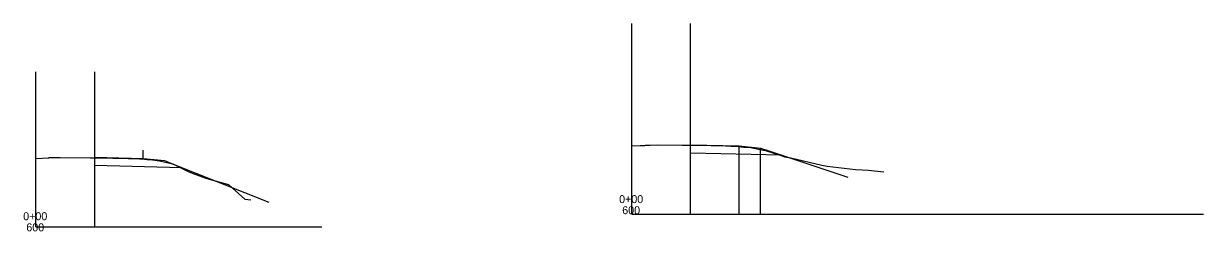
# Model space of a CAD drawing. Extents: x 2376379 to 2383101, y 559608 to 561720.
# Drawn here: x 2377931 to 2378343.8, y 561400.7 to 561473.6 of the extents above; entities that cross this region are included whole.
import ezdxf

# ---------------------------------------------------------------- set-up
doc = ezdxf.new("R2010")
doc.units = 0
for name, color, linetype in [('DT_X_Contour_Minor', 7, 'Continuous'), ('PV_X_Driveway', 7, 'Continuous'), ('SV_X_Text', 7, 'Continuous')]:
    doc.layers.add(name, color=color, linetype=linetype)

msp = doc.modelspace()

# ---------------------------------------------------------------- linework, layer by layer
at = {"layer": 'PV_X_Driveway'}
for points in [[(2378143.79, 561430.65), (2378146.66, 561430.83), (2378148.35, 561430.85), (2378148.54, 561430.93), (2378150.21, 561430.98), (2378152.65, 561430.99), (2378161.38, 561430.93), (2378164.12, 561430.92), (2378166.6, 561430.89), (2378176.62, 561430.7), (2378178.51, 561430.61), (2378180.39, 561430.55), (2378181.06, 561430.42), (2378182.95, 561430.25), (2378184.95, 561430.17), (2378188.59, 561429.37), (2378190.62, 561429.07), (2378196.1, 561427.35), (2378197.27, 561426.88), (2378199.45, 561426.43), (2378210.23, 561423.92), (2378212.16, 561423.57), (2378222.08, 561422.41), (2378226.57, 561422.17), (2378231.93, 561421.59)], [(2377935.28, 561426.24), (2377939.81, 561426.54), (2377939.87, 561426.56), (2377940.21, 561426.63), (2377941.64, 561426.64), (2377943.8, 561426.64), (2377954.28, 561426.51), (2377955.51, 561426.52), (2377956.81, 561426.49), (2377967.62, 561426.27), (2377970, 561426.22), (2377971.49, 561426.17), (2377971.76, 561426.15), (2377972.4, 561426.18), (2377974.2, 561425.93), (2377976.04, 561425.73), (2377978.54, 561425.44), (2377979.03, 561425.29), (2377983.25, 561424.34), (2377988.58, 561421.75), (2377989.94, 561421.12), (2377994.78, 561419.37), (2377996.71, 561418.8), (2378002.7, 561417.18), (2378004, 561416), (2378008.36, 561412.03), (2378010.47, 561411.72)]]:
    msp.add_lwpolyline(points, dxfattribs=at)
at = {"layer": 'SV_X_Text'}
for p, q in [((2378143.79, 561406.71), (2378143.79, 561473.58)), ((2378164.36, 561406.71), (2378164.36, 561473.58)), ((2377935.28, 561402.32), (2377935.28, 561456.65)), ((2377955.85, 561402.32), (2377955.85, 561456.65)), ((2377972.85, 561426.29), (2377972.85, 561429.21)), ((2378164.36, 561431.08), (2378181.36, 561430.67)), ((2378181.36, 561406.71), (2378181.36, 561430.67)), ((2378181.36, 561430.67), (2378188.79, 561429.92)), ((2378188.79, 561406.71), (2378188.79, 561429.92)), ((2377955.85, 561426.7), (2377972.85, 561426.29)), ((2377972.85, 561426.29), (2377980.28, 561425.55)), ((2378164.36, 561428.24), (2378196.13, 561427.48)), ((2377955.85, 561423.87), (2377986.32, 561423.13)), ((2378143.79, 561406.71), (2378343.79, 561406.71)), ((2377935.28, 561402.32), (2378035.28, 561402.32))]:
    msp.add_line(p, q, dxfattribs=at)
for points in [[(2378188.79, 561429.92), (2378191.79, 561428.92), (2378219.35, 561419.74)], [(2377980.28, 561425.55), (2377982.78, 561424.55), (2378016.76, 561410.96)]]:
    msp.add_lwpolyline(points, dxfattribs=at)

# ---------------------------------------------------------------- texts
at = {"layer": 'DT_X_Contour_Minor'}
for s, p in [('0+00', (2378139.35, 561410.61)), ('600', (2378140.44, 561406.71))]:
    msp.add_text(s, height=2.8, dxfattribs=at).set_placement(p)
at = {"layer": 'SV_X_Text'}
for s, p in [('0+00', (2377930.84, 561404.61)), ('600', (2377931.94, 561400.71))]:
    msp.add_text(s, height=2.8, dxfattribs=at).set_placement(p)

doc.saveas('drawing.dxf')
